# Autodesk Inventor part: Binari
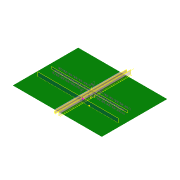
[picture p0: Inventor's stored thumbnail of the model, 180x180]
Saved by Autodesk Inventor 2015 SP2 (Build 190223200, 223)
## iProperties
Created: 2017-10
Part Number: Binari
Material: Generico
Document SubType Name: Modeling
Designer: Massimo Pizzirani
Density: 1 g/cm^3
Appearance: Bianco
Title: RAILWA~1
Creation Date: 2015-01-02
Preprocessor: ST-DEVELOPER v15
Author: Massimo Pizzirani
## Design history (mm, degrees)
node "RAILWAY CROSSING1"
sketch "Schizzo1"
  geometry: L1 (42837.43, -26182.482)-(-28214.516, -26182.482); L2 (-28214.516, -26182.482)-(-28214.516, 26039.442); L3 (-28214.516, 26039.442)-(42837.43, 26039.442); L4 (42837.43, 26039.442)-(42837.43, -26182.482); 1 further point
  constraints: 8 end point, 2 parallel, 1 horizontal, 1 perpendicular
feature "Superficie di contorno1" sketch "Schizzo1"
sketch "Schizzo5"
  geometry: L1 (33294.055, 52221.924)-(33294.055, 0); L2 (0, 0)-(71051.946, 0) reference; L3 (33294.055, 52221.924)-(38294.055, 52221.924); L4 (38294.055, 52221.924)-(38294.055, 0); L5 (71051.946, 52221.924)-(0, 52221.924) reference; 1 further point
  constraints: 6 end point, 3 point on line, 1 horizontal, 1 perpendicular, 1 vertical
  dimensions: "d9" = 5000 distance between parallel lines of L4 L1
extrude "Strada" new body sketch "Schizzo5" distance "d10" = 50; taper "d11" = 0 deg
sketch "Schizzo2"
  geometry: L1 (38549.096, 22680.618)-(39049.096, 22680.618); L2 (39049.096, 22680.618)-(39049.096, 22430.618); L3 (39049.096, 22430.618)-(38549.096, 22430.618); L4 (38549.096, 22430.618)-(38549.096, 22680.618); 1 further point
  constraints: 8 end point, 2 parallel, 1 horizontal, 1 perpendicular
  dimensions: "d0" = 500 distance of L2.end L3.end; "d1" = 250 distance of L1.end L2.end
extrude "Estrusione1" new body sketch "Schizzo2" distance "d2" = 1500; taper "d3" = 0 deg
sketch "Schizzo3"
  geometry: L1 (500, 1500)-(0, 1500) reference; L2 (250, 1500)-(250, 850.967); C1 r 25 at (250, 1300); 1 further point
  constraints: 2 end point, 1 centre point, 1 midpoint, 1 perpendicular, 1 point on line
  dimensions: "d4" = 50 diameter of C1; "d12" = 200 distance from line of L1 C1.centre
extrude "Estrusione2" join sketch "Schizzo3" distance "d5" = 50; taper "d6" = 0 deg
sketch "Schizzo4"
  geometry: C1 r 25 at (250, -1300) reference; 1 further point
extrude "Estrusione3" join sketch "Schizzo4" distance "d7" = 50; taper "d8" = 0 deg
sketch "Schizzo6"
  geometry: L1 (38549.096, 22680.618)-(38549.096, 22430.618) reference; L2 (38549.096, 22555.618)-(31262.48, 22555.618); L3 (38294.055, 0)-(38294.055, 52221.924) reference; L4 (32415.642, 22655.618)-(32615.642, 22655.618); L5 (32615.642, 22655.618)-(32615.642, 22455.618); L6 (32615.642, 22455.618)-(32415.642, 22455.618); L7 (32415.642, 22455.618)-(32415.642, 22655.618); 3 further points
  constraints: 10 end point, 2 midpoint, 2 point on line, 1 perpendicular, 9 other
  dimensions: "d13" = 200 distance of L4.start L4.end
extrude "Estrusione5" new body sketch "Schizzo6" distance "d14" = 1230; taper "d15" = 0 deg
sketch "Schizzo7"
  geometry: L1 (1230, 200)-(1230, 0) reference; L2 (1230, 200)-(1270, 200); L3 (1270, 200)-(1270, -4.403); L4 (1270, -4.403)-(1230, -4.403); L5 (1230, -4.403)-(1230, 200); L6 (1270, 200)-(1400.262, 275.193); L7 (1400.262, 275.193)-(1410.261, 257.872); L8 (1410.261, 257.872)-(1270, 176.907); L9 (1270, 97.798)-(1469.935, 97.798); L10 (1270, -4.403)-(1400.262, -79.596); L11 (1400.262, -79.596)-(1410.261, -62.275); L12 (1410.261, -62.275)-(1270, 18.69); L13 (1270, 18.69)-(1270, -4.403); 1 further point
  constraints: 24 end point, 3 perpendicular, 3 symmetric about line, 2 horizontal, 2 parallel, 1 collinear, 1 midpoint, 1 point on line
  dimensions: "d16" = 40 distance of L3.end L4.end; "d17" = 20 distance of L6.end L7.end; "d18" = 90 deg angle of L6 L7 (derived)
extrude "Estrusione6" join sketch "Schizzo7" distance "d19" = 200; taper "d20" = 0 deg
node "Piano di lavoro1"
node "Piano di lavoro2"
sketch "Schizzo8"
  geometry: C1 r 100 at (38848.031, 21538.965); 1 further point
  constraints: 1 centre point
  dimensions: "d21" = 200 diameter of C1
extrude "Estrusione7" new body sketch "Schizzo8" distance "d22" = 3000; taper "d23" = 0 deg
node "Piano di lavoro3"
sketch "Schizzo9"
  geometry: C1 r 100 at (0, 0) reference; C2 r 100 at (0, 0); C3 r 107.5 at (0, 0); 1 further point
  constraints: 2 centre point, 2 coincident
  dimensions: "d25" = 215 diameter of C3
extrude "Estrusione8" join sketch "Schizzo9" distance "d26" = 150; taper "d27" = 0 deg
sketch "Schizzo10"
  geometry: L1 (0.38, -99.999)-(450.295, -99.999); L2 (450.295, -99.999)-(450.295, -107.5); L3 (450.295, -107.5)-(0.38, -107.5); L4 (0.38, -107.5)-(0.38, -99.999); C1 r 107.5 at (0, 0) reference; 3 further points
  constraints: 8 end point, 2 parallel, 1 horizontal, 1 perpendicular, 4 other
extrude "Estrusione9" join sketch "Schizzo10" distance "d28" = 20; taper "d29" = 0 deg
sketch "Schizzo11"
  geometry: L1 (449.914, 0)-(0, 0) reference; L2 (449.914, -250)-(449.914, 0); L3 (449.914, 0)-(449.914, -20) reference; C1 r 250 at (449.914, -250); 1 further point
  constraints: 2 end point, 1 centre point, 1 collinear, 1 tangent
  dimensions: "d32" = 500 diameter of C1
extrude "Estrusione10" join sketch "Schizzo11" distance "d30" = 20; taper "d31" = 0 deg
sketch "Schizzo12"
  geometry: C1 r 125 at (0, 0); C2 r 140 at (0, 0); 1 further point
  constraints: 2 centre point, 1 coincident
  dimensions: "d33" = 250 diameter of C1; "d34" = 15 radial gap between concentric circles of C2 C1
extrude "Estrusione11" join sketch "Schizzo12" distance "d35" = 300; taper "d36" = 0 deg
node "Piano di lavoro4"
  node "Asse di lavoro1"
sketch "Schizzo13"
  geometry: L1 (-20, 250)-(-20, -250) reference; L2 (-20, -26.712)-(-223.027, 18.852); L3 (-320, 140)-(-320, -140) reference; L4 (-320, 140)-(-371.602, 140); L5 (-371.602, 140)-(-371.602, -153.009); L6 (-371.602, -153.009)-(-20, -153.009); L7 (-20, -153.009)-(-20, -26.712); A1 r 124.161 centre (-195.839, 140) between (-320, 140) and (-223.027, 18.852); 1 further point
  constraints: 10 end point, 2 perpendicular, 2 point on circle, 2 point on line, 2 tangent, 1 centre point, 1 collinear, 1 horizontal
extrude "Estrusione12" cut sketch "Schizzo13" stored distance "d38" = 300; taper "d39" = 0 deg
sketch "Schizzo14"
  geometry: 3 further points
  constraints: 3 other
extrude "Estrusione13" join sketch "Schizzo14" distance "d40" = 40; taper "d42" = 0 deg; dims "d41" = 80, "d43" = 0
node "Piano di lavoro5"
sketch "Schizzo15"
  geometry: L1 (-1500, 21542.669)-(0, 21542.669); L2 (0, 21542.669)-(0, 21662.669); L3 (0, 21662.669)-(-1500, 21662.669); L4 (-1500, 21662.669)-(-1500, 21542.669); L5 (0, 0)-(0, 52221.924) reference; 1 further point
  constraints: 8 end point, 2 parallel, 1 horizontal, 1 perpendicular, 1 point on line
  dimensions: "d45" = 1500 distance of L3.end L2.end; "d46" = 120 distance of L2.end L1.end
extrude "Estrusione14" join sketch "Schizzo15" distance "d47" = 40; taper "d48" = 0 deg
chamfer "Smusso1" distance "d49" = 60; stored, may be unused: second distance "d50" = 2, angle "d51" = 45 deg
pattern_linear "Serie rettangolare1"
sketch "Schizzo16"
  geometry: L1 (40294.055, 24042.669)-(40334.055, 24042.669) reference; L2 (40334.055, 24162.669)-(40294.055, 24162.669) reference; L3 (40334.055, 24162.669)-(40294.055, 24042.669); L4 (40374.055, 24077.669)-(40254.055, 24077.669); L5 (40254.055, 24077.669)-(40254.055, 24127.669); L6 (40254.055, 24127.669)-(40374.055, 24127.669); L7 (40374.055, 24127.669)-(40374.055, 24077.669); L8 (40374.055, 24077.669)-(40254.055, 24127.669); L9 (40254.055, 24077.669)-(40374.055, 24127.669); 2 further points
  constraints: 14 end point, 3 midpoint, 2 parallel, 1 horizontal, 1 perpendicular
  dimensions: "d55" = 120 distance of L5.end L6.end; "d56" = 50 distance of L4.end L5.end
extrude "Estrusione15" join sketch "Schizzo16" distance "d57" = 1500; taper "d58" = 0 deg
chamfer "Smusso2" distance "d59" = 60; stored, may be unused: second distance "d60" = 2, angle "d61" = 45 deg
sketch "Schizzo17"
  geometry: L1 (40294.055, 21542.669)-(40334.055, 21542.669) reference; L2 (40334.055, 21662.669)-(40294.055, 21662.669) reference; L3 (40314.055, 21542.669)-(40314.055, 21662.669); L4 (40374.055, 21662.669)-(40254.055, 21662.669); L5 (40254.055, 21662.669)-(40254.055, 21542.669); L6 (40254.055, 21542.669)-(40374.055, 21542.669); L7 (40374.055, 21542.669)-(40374.055, 21662.669); L8 (40374.055, 21662.669)-(40254.055, 21542.669); L9 (40254.055, 21662.669)-(40374.055, 21542.669); L10 (40294.055, 24042.669)-(40334.055, 24042.669) reference; L11 (40334.055, 24162.669)-(40294.055, 24162.669) reference; L12 (40374.055, 24077.669)-(40374.055, 24127.669) reference; L13 (40254.055, 24127.669)-(40254.055, 24077.669) reference; L14 (40374.055, 24162.669)-(40254.055, 24162.669); L15 (40254.055, 24162.669)-(40254.055, 24042.669); L16 (40254.055, 24042.669)-(40374.055, 24042.669); L17 (40374.055, 24042.669)-(40374.055, 24162.669); L18 (40374.055, 24162.669)-(40254.055, 24042.669); L19 (40254.055, 24162.669)-(40374.055, 24042.669); 3 further points
  constraints: 26 end point, 7 midpoint, 4 parallel, 2 horizontal, 2 perpendicular
  dimensions: "d65" = 120 distance of L6.end L5.end; "d66" = 120 distance of L5.end L4.end
extrude "Estrusione16" join sketch "Schizzo17" distance "d67" = 1500; taper "d68" = 0 deg
chamfer "Smusso3" distance "d69" = 30; stored, may be unused: second distance "d70" = 2, angle "d71" = 45 deg
node "Piano di lavoro6"
sketch "Schizzo18"
  geometry: L1 (-1200, -456.22)-(-1100, -456.22); L2 (-1100, -456.22)-(-1100, 2065.674); L3 (-1100, 2065.674)-(-1200, 2065.674); L4 (-1200, 2065.674)-(-1200, -456.22); L5 (-350, -456.22)-(-250, -456.22); L6 (-250, -456.22)-(-250, 2065.674); L7 (-250, 2065.674)-(-350, 2065.674); L8 (-350, 2065.674)-(-350, -456.22); L9 (-1470, -500)-(-1470, -380) reference; L10 (0, -500)-(-1470, -500) reference; L11 (0, -500)-(0, -380) reference; L12 (0, -380)-(-1470, -380) reference; 1 further point
  constraints: 16 end point, 4 parallel, 2 horizontal, 2 perpendicular
  dimensions: "d73" = 100 distance of L3.end L2.end; "d74" = 100 distance between parallel lines of L8 L6; "d75" = 1100 distance between parallel lines of L11 L2; "d76" = 250 distance between parallel lines of L11 L6
extrude "Estrusione17" join sketch "Schizzo18" stored distance "d77" = 30; taper "d78" = 0 deg
node "Piano di lavoro7"
sketch "Schizzo19"
  geometry: L1 (-425, 1200)-(-425, 1100) reference; L2 (-425, 350)-(-425, 250) reference; L3 (-425, 1200)-(24076.272, 1200); L4 (24076.272, 1200)-(24076.272, 1100); L5 (24076.272, 1100)-(-425, 1100); L6 (-425, 1100)-(-425, 1200); L7 (-425, 350)-(24076.272, 350); L8 (24076.272, 350)-(24076.272, 250); L9 (24076.272, 250)-(-425, 250); L10 (-425, 250)-(-425, 350); 1 further point
  constraints: 16 end point, 4 parallel, 2 horizontal, 2 perpendicular
extrude "Estrusione18" join sketch "Schizzo19" stored distance "d80" = 30; taper "d81" = 0 deg
node "Piano di lavoro8"
mirror "Specchio1"
node "Asse di lavoro2"
sketch "Schizzo20"
  geometry: C1 r 40 at (39452.103, 16316.842); 1 further point
  constraints: 1 centre point
  dimensions: "d86" = 80 diameter of C1
extrude "Estrusione19" new body sketch "Schizzo20" distance "d87" = 3000; taper "d88" = 0 deg
node "Piano di lavoro9"
sketch "Schizzo21"
  geometry: L1 (0, 2887.397)-(514.484, 3125.514); L2 (0, 2845.031)-(500.453, 3076.654); L3 (236.393, 2770.368)-(600.797, 2939.024); L4 (144.855, 2770.368)-(554.468, 2959.948); L5 (514.484, 3125.514)-(654.203, 3076.96); L6 (654.203, 3076.96)-(600.797, 2939.024); L7 (500.453, 3076.654)-(554.468, 2959.948); L8 (0, 2653.339)-(514.484, 2415.223); L9 (0, 2695.706)-(500.453, 2464.083); L10 (236.393, 2770.368)-(600.797, 2601.713); L11 (144.855, 2770.368)-(554.468, 2580.789); L12 (514.484, 2415.223)-(654.203, 2463.776); L13 (654.203, 2463.776)-(600.797, 2601.713); L14 (500.453, 2464.083)-(554.468, 2580.789); L15 (0, 2887.397)-(-514.484, 3125.514); L16 (0, 2845.031)-(-500.453, 3076.654); L17 (-236.393, 2770.368)-(-600.797, 2939.024); L18 (-144.855, 2770.368)-(-554.468, 2959.948); L19 (-514.484, 3125.514)-(-654.203, 3076.96); L20 (-654.203, 3076.96)-(-600.797, 2939.024); L21 (-500.453, 3076.654)-(-554.468, 2959.948); L22 (0, 2653.339)-(-514.484, 2415.223); L23 (0, 2695.706)-(-500.453, 2464.083); L24 (-236.393, 2770.368)-(-600.797, 2601.713); L25 (-144.855, 2770.368)-(-554.468, 2580.789); L26 (-514.484, 2415.223)-(-654.203, 2463.776); L27 (-654.203, 2463.776)-(-600.797, 2601.713); L28 (-500.453, 2464.083)-(-554.468, 2580.789); L29 (40, 3000)-(-40, 3000) reference; L30 (0, 3000)-(0, 1677.425); L31 (0, 2845.031)-(0, 3435.634); 1 further point
  constraints: 60 end point, 2 point on line, 1 midpoint, 1 vertical
extrude "Estrusione20" join sketch "Schizzo21" distance "d89" = 20; taper "d90" = 0 deg
extrude "Estrusione21" join sketch "Schizzo21" distance "d91" = 0.01; taper "d92" = 0 deg
sketch "Schizzo22"
  geometry: L1 (33294.055, 52221.924)-(33294.055, 0) reference; L2 (33294.055, 0)-(38294.055, 0) reference; L3 (38294.055, 0)-(38294.055, 52221.924) reference; L4 (38294.055, 52221.924)-(33294.055, 52221.924) reference; L5 (0, 0)-(71051.946, 0) reference; L6 (35744.055, 0)-(35744.055, 20437.21); L7 (35744.055, 20437.21)-(38294.055, 20437.21); L8 (38294.055, 0)-(38294.055, 52221.924) reference; L9 (38294.055, 19937.21)-(35844.055, 19937.21); L10 (35844.055, 19937.21)-(35844.055, 0); L11 (33294.055, 49812.461)-(38294.055, 49812.461); L12 (35794.055, 49812.461)-(35794.055, -19184.075); L13 (37069.055, 19937.21)-(37069.055, 8149.755); L14 (37910.549, 12665.619)-(36321.529, 17031.417); L15 (36321.529, 17031.417)-(36227.56, 16997.215); L16 (36227.56, 16997.215)-(37816.58, 12631.417); L17 (37816.58, 12631.417)-(37910.549, 12665.619); L18 (37910.549, 12665.619)-(36227.56, 16997.215); L19 (36321.529, 17031.417)-(37816.58, 12631.417); L20 (36227.56, 12665.619)-(37816.58, 17031.417); L21 (37816.58, 17031.417)-(37910.549, 16997.215); L22 (37910.549, 16997.215)-(36321.529, 12631.417); L23 (36321.529, 12631.417)-(36227.56, 12665.619); L24 (36227.56, 12665.619)-(37910.549, 16997.215); L25 (37816.58, 17031.417)-(36321.529, 12631.417); L26 (35201.085, 15531.417)-(36408.114, 15531.417); L27 (35135.6, 14131.417)-(38897.636, 14131.417); L28 (36166.956, 15531.417)-(36266.956, 15531.417); L29 (36266.956, 15531.417)-(36266.956, 14131.417); L30 (36266.956, 14131.417)-(36166.956, 14131.417); L31 (36166.956, 14131.417)-(36166.956, 15531.417); L32 (37554.813, 15531.417)-(37654.813, 15531.417); L33 (37654.813, 15531.417)-(37654.813, 14131.417); L34 (37654.813, 14131.417)-(37554.813, 14131.417); L35 (37554.813, 14131.417)-(37554.813, 15531.417); L36 (37654.813, 14131.417)-(37970.081, 14131.417); L37 (37970.081, 14131.417)-(37970.081, 14231.417); L38 (37970.081, 14231.417)-(37654.813, 14231.417); L39 (37654.813, 14231.417)-(37654.813, 14131.417); L40 (36608.114, 15331.417)-(36608.114, 15031.417); L41 (36408.114, 14831.417)-(36266.956, 14831.417); L42 (36508.114, 15331.417)-(36508.114, 15031.417); L43 (36408.114, 14931.417)-(36266.956, 14931.417); L44 (36266.956, 15431.417)-(36408.114, 15431.417); L45 (36266.956, 15531.417)-(38651.293, 15531.417); L46 (36266.956, 15531.417)-(36408.114, 15531.417); L47 (35744.055, 0)-(35844.055, 0); L48 (38294.055, 20437.21)-(38294.055, 19937.21); A1 r 200 centre (36408.114, 15331.417) between (36608.114, 15331.417) and (36408.114, 15531.417); A2 r 200 centre (36408.114, 15031.417) between (36408.114, 14831.417) and (36608.114, 15031.417); A3 r 100 centre (36408.114, 15331.417) between (36508.114, 15331.417) and (36408.114, 15431.417); A4 r 100 centre (36408.114, 15031.417) between (36408.114, 14931.417) and (36508.114, 15031.417); 3 further points
  constraints: 84 end point, 13 point on line, 11 parallel, 11 perpendicular, 8 midpoint, 8 point on circle, 8 tangent, 7 horizontal, 4 centre point, 2 collinear, 2 equal radius, 2 vertical
  dimensions: "d94" = 100 distance between parallel lines of L6 L10; "d95" = 50 distance between parallel lines of L10 L12; "d96" = 500 distance between parallel lines of L7 L9; "d97" = 100 distance of L15.end L14.end; "d98" = 100 distance of L20.end L21.end; "d99" = 2200 vertical distance of point (37069.055, 14831.417) L20.end; "d100" = 20 deg angle of L13 L20; "d101" = 20 deg angle of L14 L13 (= d100); "d102" = 2200 vertical distance of point (37069.055, 14831.417) L14.end; "d103" = 700 distance from line of point (37069.055, 14831.417) L26; "d104" = 700 distance from line of L27 point (37069.055, 14831.417); "d105" = 100 distance of L29.end L30.end; "d106" = 100 distance of L33.end L34.end; "d107" = 100 distance of L37.end L36.end; "d108" = 100 distance between parallel lines of L40 L42; "d109" = 100 distance between parallel lines of L44 L26; "d110" = 200 radius of A1; "d111" = 100 radius of A3
extrude "Estrusione22" join sketch "Schizzo22" distance "d112" = 0.01; taper "d113" = 0 deg
pattern_circular "Serie circolare2" dims "d115" = 360 deg
sketch "Schizzo23"
  geometry: L1 (5000, 18774.18)-(-17.865, 18774.18); L2 (-17.865, 18774.18)-(-17.865, 20722.801); L3 (-17.865, 20722.801)-(5000, 20722.801); L4 (5000, 20722.801)-(5000, 18774.18); 1 further point
  constraints: 8 end point, 2 parallel, 1 horizontal, 1 perpendicular
extrude "Estrusione23" cut sketch "Schizzo23" distance "d117" = 0.01; taper "d118" = 0 deg
node "brep_1"
pattern_linear "Serie rettangolare2"
pattern_circular "Serie circolare1" dims "d84" = 360 deg
node "brep_255"
node "brep_256"
node "brep_257"
node "brep_258"
node "brep_259"
node "brep_260"
node "brep_261"
node "brep_262"
node "brep_263"
node "brep_264"
node "brep_265"
node "brep_266"
node "brep_267"
node "brep_268"
node "brep_269"
node "brep_270"
node "brep_271"
node "brep_272"
node "brep_273"
node "brep_274"
node "brep_275"
node "brep_276"
node "brep_277"
node "brep_278"
node "brep_279"
node "brep_280"
node "brep_281"
node "brep_282"
node "brep_283"
node "brep_284"
node "brep_285"
node "brep_286"
node "brep_287"
node "brep_288"
node "brep_289"
node "brep_290"
node "brep_291"
node "brep_292"
node "brep_293"
node "brep_294"
node "brep_295"
node "brep_296"
node "brep_297"
node "brep_298"
node "brep_299"
node "brep_300"
node "brep_301"
node "brep_302"
node "brep_303"
node "brep_304"
node "brep_305"
node "brep_306"
node "brep_307"
node "brep_308"
node "brep_309"
node "brep_310"
node "brep_311"
node "brep_312"
node "brep_313"
node "brep_314"
node "brep_315"
node "brep_316"
node "brep_317"
node "brep_318"
node "brep_319"
node "brep_320"
node "brep_321"
node "brep_322"
node "brep_323"
node "brep_462"
node "brep_463"
node "Base255"
node "Base256"
node "Base257"
node "Base258"
node "Base259"
node "Base260"
node "Base261"
node "Base262"
node "Base263"
node "Base264"
node "Base265"
node "Base266"
node "Base267"
node "Base268"
node "Base269"
node "Base270"
node "Base271"
node "Base272"
node "Base273"
node "Base274"
node "Base275"
node "Base276"
node "Base277"
node "Base278"
node "Base279"
node "Base280"
node "Base281"
node "Base282"
node "Base283"
node "Base284"
node "Base285"
node "Base286"
node "Base287"
node "Base288"
node "Base289"
node "Base290"
node "Base291"
node "Base292"
node "Base293"
node "Base294"
node "Base295"
node "Base296"
node "Base297"
node "Base298"
node "Base299"
node "Base300"
node "Base301"
node "Base302"
node "Base303"
node "Base304"
node "Base305"
node "Base306"
node "Base307"
node "Base308"
node "Base309"
node "Base310"
node "Base311"
node "Base312"
node "Base313"
node "Base314"
node "Base315"
node "Base316"
node "Base317"
node "Base318"
node "Base319"
node "Base320"
node "Base321"
node "Base322"
node "Base323"
node "Base462"
node "Base463"
node "Superficie2"
node "Solido542"
node "Solido543"
node "Solido544"
node "Solido545"
node "Linea chiusa proiettata1"
node "Solido546"
node "Linea chiusa proiettata2"
other parameters: "d37" = 90 deg
